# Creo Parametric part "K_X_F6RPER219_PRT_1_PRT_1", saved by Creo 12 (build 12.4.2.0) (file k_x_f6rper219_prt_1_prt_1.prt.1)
Units: Custom; MM, KILOGRAM, SECS

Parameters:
  PTC_WM_ITERATION = "0"
  PTC_WM_VERSION = "-.0"
  PTC_WM_LIFECYCLE_STATE = "In Work"
  PTC_WM_LIFECYCLE = "MO_CADDocument"
  PTC_WM_CREATED_BY = "Maximilian Roepper (Z0017RMS: MO)"
  PTC_WM_CREATED_ON = "18-Sep-26 11:36:42 AM"
  PTC_WM_MODIFIED_BY = "Maximilian Roepper (Z0017RMS: MO)"
  PTC_WM_MODIFIED_ON = "18-Sep-26 11:36:46 AM"
  PDMLINKNUMBER = "PDM000071455156"
  PTC_WM_NAME = "k_x_f6rper219_prt_1_prt_1.prt"
  PTC_WM_NUMBER = "PDM000071455156"

Other parameters: WEIGHT, WEIGHT_FACTOR, WEIGHT_ADD, _MASS_TEMP, _DIFF_TEMP, MC_ERRORS, SUPPLIER

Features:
  1. coordinate system
  2. datum plane "PRT_YZ"
  3. datum plane "PRT_XY"
  4. datum plane "PRT_XZ"
  5. coordinate system
  6. datum axis
  7. datum axis
  8. datum axis
  9. coordinate system
  10. imported feature
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
Other named items: PRT, SIEMENS_MO, DRW_VIEW_ORG, PRT_X, PRT_Y, PRT_Z, CS0, ROUGH_GROB

Layers: 00_STD_CSYS-KSYS, 01_STD_PLANES-EBENEN, 02_STD_AXES-ACHSEN, 03_STD_CSYS-KSYS, 24_IMPORT_FEAT-IMPORT_KE

Surfaces: 20 tabulated cylinder, 4 plane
